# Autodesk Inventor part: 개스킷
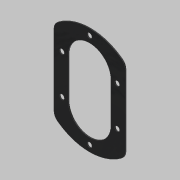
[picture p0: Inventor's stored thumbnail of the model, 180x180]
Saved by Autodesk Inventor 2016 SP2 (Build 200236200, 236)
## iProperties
Created: 2019-03
Part Number: 개스킷
Material: 고무
Document SubType Name: Modeling
Designer: mduedu
Density: 1 g/cm^3
Appearance: 고무 - 검은색 - 버전 1.1
Author: mduedu
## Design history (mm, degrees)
sketch "스케치1"
  geometry: L1 (-44.721, -40)-(44.721, -40); L2 (44.721, 40)-(-44.721, 40); A1 r 60 centre (0, 0) between (44.721, -40) and (44.721, 40); A2 r 60 centre (0, 0) between (-44.721, 40) and (-44.721, -40); 5 further points
  constraints: 6 point on circle, 4 end point, 2 centre point, 2 coincident, 2 horizontal alignment, 2 midpoint, 2 vertical alignment, 1 horizontal, 1 parallel
  dimensions: "d0" = 60 radius of A1; "d2" = 80 distance between parallel lines of L2 L1
extrude "돌출1" new body sketch "스케치1" distance "d3" = 1; taper "d4" = 0 deg
fillet "모깎기1" dims "d5" = 10
sketch "스케치2" dims "d6" = 48
  geometry: L1 (-24, -22)-(24, -22); L2 (24, -22)-(24, 22); L3 (24, 22)-(-24, 22); L4 (-24, 22)-(-24, -22); L5 (-24, -22)-(24, 22); L6 (24, -22)-(-24, 22); 3 further points
  constraints: 12 end point, 4 midpoint, 2 horizontal alignment, 2 parallel, 1 horizontal, 1 perpendicular, 4 other
  dimensions: "d8" = 22 distance from line of L3 point (0, 0)
extrude "돌출2" cut sketch "스케치2" stored distance "d9" = 1; taper "d10" = 0 deg
sketch "스케치3" dims "d0" = 60, "d2" = 80
  geometry: L1 (31, -22)-(31, 22); L2 (-31, 22)-(-31, -22); L3 (-31, -22)-(31, 22); L4 (31, -22)-(-31, 22); A1 r 31 centre (0, 22) between (31, 22) and (-31, 22); A2 r 31 centre (0, -22) between (-31, -22) and (31, -22); 8 further points
  constraints: 8 end point, 6 point on circle, 4 coincident, 4 midpoint, 3 tangent, 2 centre point, 2 vertical alignment, 1 parallel
  dimensions: "d11" = 31 radius of A1; "d13" = 44 distance of A2.centre A1.centre
hole "구멍1" sketch "스케치3" at (-31, 22), (-31, -22), (31, -22), (31, 22), (0, -53), (0, 53) diameter "d14" = 5.5; stored, may be unused: countersink angle "d18" = 90 deg, drill point angle "d20" = 118 deg; dims "d15" = 6, "d16" = 4, "d17" = 2, "d19" = 8
node "솔리드1"
